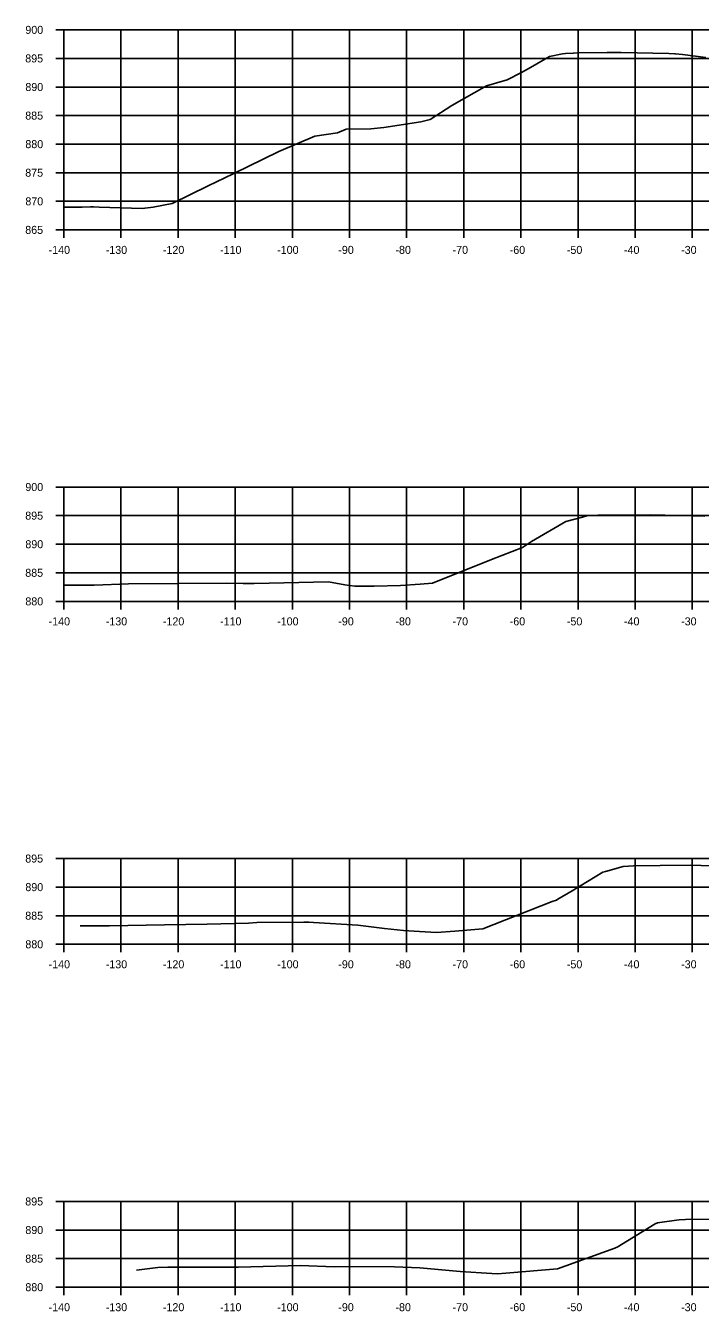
# Model space of a CAD drawing. Extents: x 1098669 to 1198896, y 698679 to 704410.
# Drawn here: x 1113352.2 to 1113470.3, y 701729.3 to 701954.3 of the extents above; entities that cross this region are included whole.
import ezdxf

# ---------------------------------------------------------------- set-up
doc = ezdxf.new("R2010")
doc.units = 0
for name, color, linetype in [('R_Alt Surface', 7, 'Continuous'), ('R_Axis', 7, 'Continuous'), ('R_Axis Annot', 7, 'Continuous'), ('R_Grid', 7, 'Continuous')]:
    doc.layers.add(name, color=color, linetype=linetype)

msp = doc.modelspace()

# ---------------------------------------------------------------- linework, layer by layer
at = {"layer": 'R_Alt Surface'}
for points in [[(1113358.87, 701922.53), (1113362.08, 701922.56), (1113363.56, 701922.57), (1113364.04, 701922.57), (1113365.05, 701922.54), (1113372.57, 701922.32), (1113374.49, 701922.56), (1113377.86, 701923.2), (1113384.13, 701926.27), (1113388.49, 701928.38), (1113396.52, 701932.3), (1113402.82, 701934.94), (1113406.77, 701935.56), (1113408.29, 701936.2), (1113412.61, 701936.25), (1113414.86, 701936.46), (1113421.38, 701937.47), (1113422.98, 701937.86), (1113426.78, 701940.31), (1113432.82, 701943.74), (1113436.49, 701944.84), (1113438.98, 701946.1), (1113440.53, 701946.98), (1113443.9, 701948.9), (1113446.15, 701949.37), (1113446.7, 701949.45), (1113447.99, 701949.49), (1113448.07, 701949.49), (1113448.95, 701949.51), (1113453.98, 701949.57), (1113456.41, 701949.6), (1113464.77, 701949.41), (1113465.8, 701949.38), (1113465.95, 701949.37), (1113467.16, 701949.25), (1113471.22, 701948.74)], [(1113358.87, 701856.38), (1113364.16, 701856.37), (1113370.18, 701856.63), (1113387.33, 701856.72), (1113390.25, 701856.68), (1113392.19, 701856.67), (1113405.17, 701856.96), (1113408.04, 701856.48), (1113409.81, 701856.23), (1113413.19, 701856.24), (1113417.78, 701856.33), (1113421.22, 701856.59), (1113423.41, 701856.77), (1113433.7, 701860.86), (1113439.14, 701863.01), (1113440.73, 701864.02), (1113446.74, 701867.56), (1113449.65, 701868.32), (1113450.59, 701868.56), (1113451.06, 701868.57), (1113452.36, 701868.62), (1113454.8, 701868.64), (1113461.57, 701868.7), (1113464.06, 701868.63), (1113471.04, 701868.46)], [(1113361.74, 701796.79), (1113366.86, 701796.79), (1113376.52, 701796.99), (1113383.94, 701797.08), (1113391.18, 701797.24), (1113392.65, 701797.36), (1113400.85, 701797.44), (1113401.75, 701797.43), (1113402.59, 701797.38), (1113410.3, 701796.93), (1113415.02, 701796.35), (1113418.3, 701795.99), (1113421.13, 701795.81), (1113424.08, 701795.65), (1113427.28, 701795.87), (1113432.2, 701796.27), (1113444.34, 701801.02), (1113445.09, 701801.3), (1113445.33, 701801.45), (1113447.82, 701802.94), (1113453.18, 701806.16), (1113453.7, 701806.31), (1113456.74, 701807.15), (1113457.67, 701807.22), (1113458.6, 701807.28), (1113463.25, 701807.33), (1113468.57, 701807.4), (1113474.18, 701807.25)], [(1113371.62, 701736.53), (1113375.32, 701737), (1113377.06, 701737.07), (1113389.45, 701737.07), (1113400.27, 701737.33), (1113406.17, 701737.12), (1113408.76, 701737.17), (1113416.72, 701737.1), (1113421.16, 701736.92), (1113426.31, 701736.48), (1113428.24, 701736.3), (1113433.8, 701735.95), (1113434.77, 701735.88), (1113436.24, 701736.01), (1113445.25, 701736.79), (1113455.33, 701740.41), (1113455.53, 701740.49), (1113455.69, 701740.58), (1113457.52, 701741.69), (1113462.38, 701744.62), (1113462.75, 701744.83), (1113463.2, 701744.9), (1113466.09, 701745.31), (1113466.54, 701745.34), (1113467.68, 701745.41), (1113472.5, 701745.48)]]:
    msp.add_lwpolyline(points, dxfattribs=at)
at = {"layer": 'R_Axis'}
for p, q in [((1113357.47, 701953.56), (1113358.87, 701953.56)), ((1113358.87, 701918.56), (1113358.87, 701953.56)), ((1113357.47, 701948.56), (1113358.87, 701948.56)), ((1113357.47, 701943.56), (1113358.87, 701943.56)), ((1113357.47, 701938.56), (1113358.87, 701938.56)), ((1113357.47, 701933.56), (1113358.87, 701933.56)), ((1113357.47, 701928.56), (1113358.87, 701928.56)), ((1113357.47, 701923.56), (1113358.87, 701923.56)), ((1113357.47, 701918.56), (1113358.87, 701918.56)), ((1113358.87, 701918.56), (1113638.87, 701918.56)), ((1113358.87, 701917.16), (1113358.87, 701918.56)), ((1113368.87, 701917.16), (1113368.87, 701918.56)), ((1113378.87, 701917.16), (1113378.87, 701918.56)), ((1113388.87, 701917.16), (1113388.87, 701918.56)), ((1113398.87, 701917.16), (1113398.87, 701918.56)), ((1113408.87, 701917.16), (1113408.87, 701918.56)), ((1113418.87, 701917.16), (1113418.87, 701918.56)), ((1113428.87, 701917.16), (1113428.87, 701918.56)), ((1113438.87, 701917.16), (1113438.87, 701918.56)), ((1113448.87, 701917.16), (1113448.87, 701918.56)), ((1113458.87, 701917.16), (1113458.87, 701918.56)), ((1113468.87, 701917.16), (1113468.87, 701918.56)), ((1113357.47, 701873.56), (1113358.87, 701873.56)), ((1113358.87, 701853.56), (1113358.87, 701873.56)), ((1113357.47, 701868.56), (1113358.87, 701868.56)), ((1113357.47, 701863.56), (1113358.87, 701863.56)), ((1113357.47, 701858.56), (1113358.87, 701858.56)), ((1113357.47, 701853.56), (1113358.87, 701853.56)), ((1113358.87, 701853.56), (1113638.87, 701853.56)), ((1113358.87, 701852.16), (1113358.87, 701853.56)), ((1113368.87, 701852.16), (1113368.87, 701853.56)), ((1113378.87, 701852.16), (1113378.87, 701853.56)), ((1113388.87, 701852.16), (1113388.87, 701853.56)), ((1113398.87, 701852.16), (1113398.87, 701853.56)), ((1113408.87, 701852.16), (1113408.87, 701853.56)), ((1113418.87, 701852.16), (1113418.87, 701853.56)), ((1113428.87, 701852.16), (1113428.87, 701853.56)), ((1113438.87, 701852.16), (1113438.87, 701853.56)), ((1113448.87, 701852.16), (1113448.87, 701853.56)), ((1113458.87, 701852.16), (1113458.87, 701853.56)), ((1113468.87, 701852.16), (1113468.87, 701853.56)), ((1113357.47, 701808.56), (1113358.87, 701808.56)), ((1113358.87, 701793.56), (1113358.87, 701808.56)), ((1113357.47, 701803.56), (1113358.87, 701803.56)), ((1113357.47, 701798.56), (1113358.87, 701798.56)), ((1113357.47, 701793.56), (1113358.87, 701793.56)), ((1113358.87, 701793.56), (1113638.87, 701793.56)), ((1113358.87, 701792.16), (1113358.87, 701793.56)), ((1113368.87, 701792.16), (1113368.87, 701793.56)), ((1113378.87, 701792.16), (1113378.87, 701793.56)), ((1113388.87, 701792.16), (1113388.87, 701793.56)), ((1113398.87, 701792.16), (1113398.87, 701793.56)), ((1113408.87, 701792.16), (1113408.87, 701793.56)), ((1113418.87, 701792.16), (1113418.87, 701793.56)), ((1113428.87, 701792.16), (1113428.87, 701793.56)), ((1113438.87, 701792.16), (1113438.87, 701793.56)), ((1113448.87, 701792.16), (1113448.87, 701793.56)), ((1113458.87, 701792.16), (1113458.87, 701793.56)), ((1113468.87, 701792.16), (1113468.87, 701793.56)), ((1113357.47, 701748.56), (1113358.87, 701748.56)), ((1113358.87, 701733.56), (1113358.87, 701748.56)), ((1113357.47, 701743.56), (1113358.87, 701743.56)), ((1113357.47, 701738.56), (1113358.87, 701738.56)), ((1113357.47, 701733.56), (1113358.87, 701733.56)), ((1113358.87, 701733.56), (1113638.87, 701733.56)), ((1113358.87, 701732.16), (1113358.87, 701733.56)), ((1113368.87, 701732.16), (1113368.87, 701733.56)), ((1113378.87, 701732.16), (1113378.87, 701733.56)), ((1113388.87, 701732.16), (1113388.87, 701733.56)), ((1113398.87, 701732.16), (1113398.87, 701733.56)), ((1113408.87, 701732.16), (1113408.87, 701733.56)), ((1113418.87, 701732.16), (1113418.87, 701733.56)), ((1113428.87, 701732.16), (1113428.87, 701733.56)), ((1113438.87, 701732.16), (1113438.87, 701733.56)), ((1113448.87, 701732.16), (1113448.87, 701733.56)), ((1113458.87, 701732.16), (1113458.87, 701733.56)), ((1113468.87, 701732.16), (1113468.87, 701733.56))]:
    msp.add_line(p, q, dxfattribs=at)
at = {"layer": 'R_Grid'}
for p, q in [((1113358.87, 701953.56), (1113638.87, 701953.56)), ((1113358.87, 701918.56), (1113358.87, 701953.56)), ((1113368.87, 701918.56), (1113368.87, 701953.56)), ((1113378.87, 701918.56), (1113378.87, 701953.56)), ((1113388.87, 701918.56), (1113388.87, 701953.56)), ((1113398.87, 701918.56), (1113398.87, 701953.56)), ((1113408.87, 701918.56), (1113408.87, 701953.56)), ((1113418.87, 701918.56), (1113418.87, 701953.56)), ((1113428.87, 701918.56), (1113428.87, 701953.56)), ((1113438.87, 701918.56), (1113438.87, 701953.56)), ((1113448.87, 701918.56), (1113448.87, 701953.56)), ((1113458.87, 701918.56), (1113458.87, 701953.56)), ((1113468.87, 701918.56), (1113468.87, 701953.56)), ((1113358.87, 701948.56), (1113638.87, 701948.56)), ((1113358.87, 701943.56), (1113638.87, 701943.56)), ((1113358.87, 701938.56), (1113638.87, 701938.56)), ((1113358.87, 701933.56), (1113638.87, 701933.56)), ((1113358.87, 701928.56), (1113638.87, 701928.56)), ((1113358.87, 701923.56), (1113638.87, 701923.56)), ((1113358.87, 701918.56), (1113638.87, 701918.56)), ((1113358.87, 701873.56), (1113638.87, 701873.56)), ((1113358.87, 701853.56), (1113358.87, 701873.56)), ((1113368.87, 701853.56), (1113368.87, 701873.56)), ((1113378.87, 701853.56), (1113378.87, 701873.56)), ((1113388.87, 701853.56), (1113388.87, 701873.56)), ((1113398.87, 701853.56), (1113398.87, 701873.56)), ((1113408.87, 701853.56), (1113408.87, 701873.56)), ((1113418.87, 701853.56), (1113418.87, 701873.56)), ((1113428.87, 701853.56), (1113428.87, 701873.56)), ((1113438.87, 701853.56), (1113438.87, 701873.56)), ((1113448.87, 701853.56), (1113448.87, 701873.56)), ((1113458.87, 701853.56), (1113458.87, 701873.56)), ((1113468.87, 701853.56), (1113468.87, 701873.56)), ((1113358.87, 701868.56), (1113638.87, 701868.56)), ((1113358.87, 701863.56), (1113638.87, 701863.56)), ((1113358.87, 701858.56), (1113638.87, 701858.56)), ((1113358.87, 701853.56), (1113638.87, 701853.56)), ((1113358.87, 701808.56), (1113638.87, 701808.56)), ((1113358.87, 701793.56), (1113358.87, 701808.56)), ((1113368.87, 701793.56), (1113368.87, 701808.56)), ((1113378.87, 701793.56), (1113378.87, 701808.56)), ((1113388.87, 701793.56), (1113388.87, 701808.56)), ((1113398.87, 701793.56), (1113398.87, 701808.56)), ((1113408.87, 701793.56), (1113408.87, 701808.56)), ((1113418.87, 701793.56), (1113418.87, 701808.56)), ((1113428.87, 701793.56), (1113428.87, 701808.56)), ((1113438.87, 701793.56), (1113438.87, 701808.56)), ((1113448.87, 701793.56), (1113448.87, 701808.56)), ((1113458.87, 701793.56), (1113458.87, 701808.56)), ((1113468.87, 701793.56), (1113468.87, 701808.56)), ((1113358.87, 701803.56), (1113638.87, 701803.56)), ((1113358.87, 701798.56), (1113638.87, 701798.56)), ((1113358.87, 701793.56), (1113638.87, 701793.56)), ((1113358.87, 701748.56), (1113638.87, 701748.56)), ((1113358.87, 701733.56), (1113358.87, 701748.56)), ((1113368.87, 701733.56), (1113368.87, 701748.56)), ((1113378.87, 701733.56), (1113378.87, 701748.56)), ((1113388.87, 701733.56), (1113388.87, 701748.56)), ((1113398.87, 701733.56), (1113398.87, 701748.56)), ((1113408.87, 701733.56), (1113408.87, 701748.56)), ((1113418.87, 701733.56), (1113418.87, 701748.56)), ((1113428.87, 701733.56), (1113428.87, 701748.56)), ((1113438.87, 701733.56), (1113438.87, 701748.56)), ((1113448.87, 701733.56), (1113448.87, 701748.56)), ((1113458.87, 701733.56), (1113458.87, 701748.56)), ((1113468.87, 701733.56), (1113468.87, 701748.56)), ((1113358.87, 701743.56), (1113638.87, 701743.56)), ((1113358.87, 701738.56), (1113638.87, 701738.56)), ((1113358.87, 701733.56), (1113638.87, 701733.56))]:
    msp.add_line(p, q, dxfattribs=at)

# ---------------------------------------------------------------- texts
at = {"layer": 'R_Axis Annot'}
for s, p in [('900', (1113352.14, 701952.86)), ('895', (1113352.12, 701947.86)), ('890', (1113352.14, 701942.86)), ('885', (1113352.12, 701937.86)), ('880', (1113352.14, 701932.86)), ('875', (1113352.12, 701927.86)), ('870', (1113352.14, 701922.86)), ('865', (1113352.12, 701917.86)), ('-140', (1113356.21, 701914.36)), ('-130', (1113366.21, 701914.36)), ('-120', (1113376.21, 701914.36)), ('-110', (1113386.21, 701914.36)), ('-100', (1113396.21, 701914.36)), ('-90', (1113406.91, 701914.36)), ('-80', (1113416.91, 701914.36)), ('-70', (1113426.91, 701914.36)), ('-60', (1113436.91, 701914.36)), ('-50', (1113446.91, 701914.36)), ('-40', (1113456.91, 701914.36)), ('-30', (1113466.91, 701914.36)), ('900', (1113352.14, 701872.86)), ('895', (1113352.12, 701867.86)), ('890', (1113352.14, 701862.86)), ('885', (1113352.12, 701857.86)), ('880', (1113352.14, 701852.86)), ('-140', (1113356.21, 701849.36)), ('-130', (1113366.21, 701849.36)), ('-120', (1113376.21, 701849.36)), ('-110', (1113386.21, 701849.36)), ('-100', (1113396.21, 701849.36)), ('-90', (1113406.91, 701849.36)), ('-80', (1113416.91, 701849.36)), ('-70', (1113426.91, 701849.36)), ('-60', (1113436.91, 701849.36)), ('-50', (1113446.91, 701849.36)), ('-40', (1113456.91, 701849.36)), ('-30', (1113466.91, 701849.36)), ('895', (1113352.12, 701807.86)), ('890', (1113352.14, 701802.86)), ('885', (1113352.12, 701797.86)), ('880', (1113352.14, 701792.86)), ('-140', (1113356.21, 701789.36)), ('-130', (1113366.21, 701789.36)), ('-120', (1113376.21, 701789.36)), ('-110', (1113386.21, 701789.36)), ('-100', (1113396.21, 701789.36)), ('-90', (1113406.91, 701789.36)), ('-80', (1113416.91, 701789.36)), ('-70', (1113426.91, 701789.36)), ('-60', (1113436.91, 701789.36)), ('-50', (1113446.91, 701789.36)), ('-40', (1113456.91, 701789.36)), ('-30', (1113466.91, 701789.36)), ('895', (1113352.12, 701747.86)), ('890', (1113352.14, 701742.86)), ('885', (1113352.12, 701737.86)), ('880', (1113352.14, 701732.86)), ('-140', (1113356.21, 701729.36)), ('-130', (1113366.21, 701729.36)), ('-120', (1113376.21, 701729.36)), ('-110', (1113386.21, 701729.36)), ('-100', (1113396.21, 701729.36)), ('-90', (1113406.91, 701729.36)), ('-80', (1113416.91, 701729.36)), ('-70', (1113426.91, 701729.36)), ('-60', (1113436.91, 701729.36)), ('-50', (1113446.91, 701729.36)), ('-40', (1113456.91, 701729.36)), ('-30', (1113466.91, 701729.36))]:
    msp.add_text(s, height=1.4, dxfattribs=at).set_placement(p)

doc.saveas('drawing.dxf')
